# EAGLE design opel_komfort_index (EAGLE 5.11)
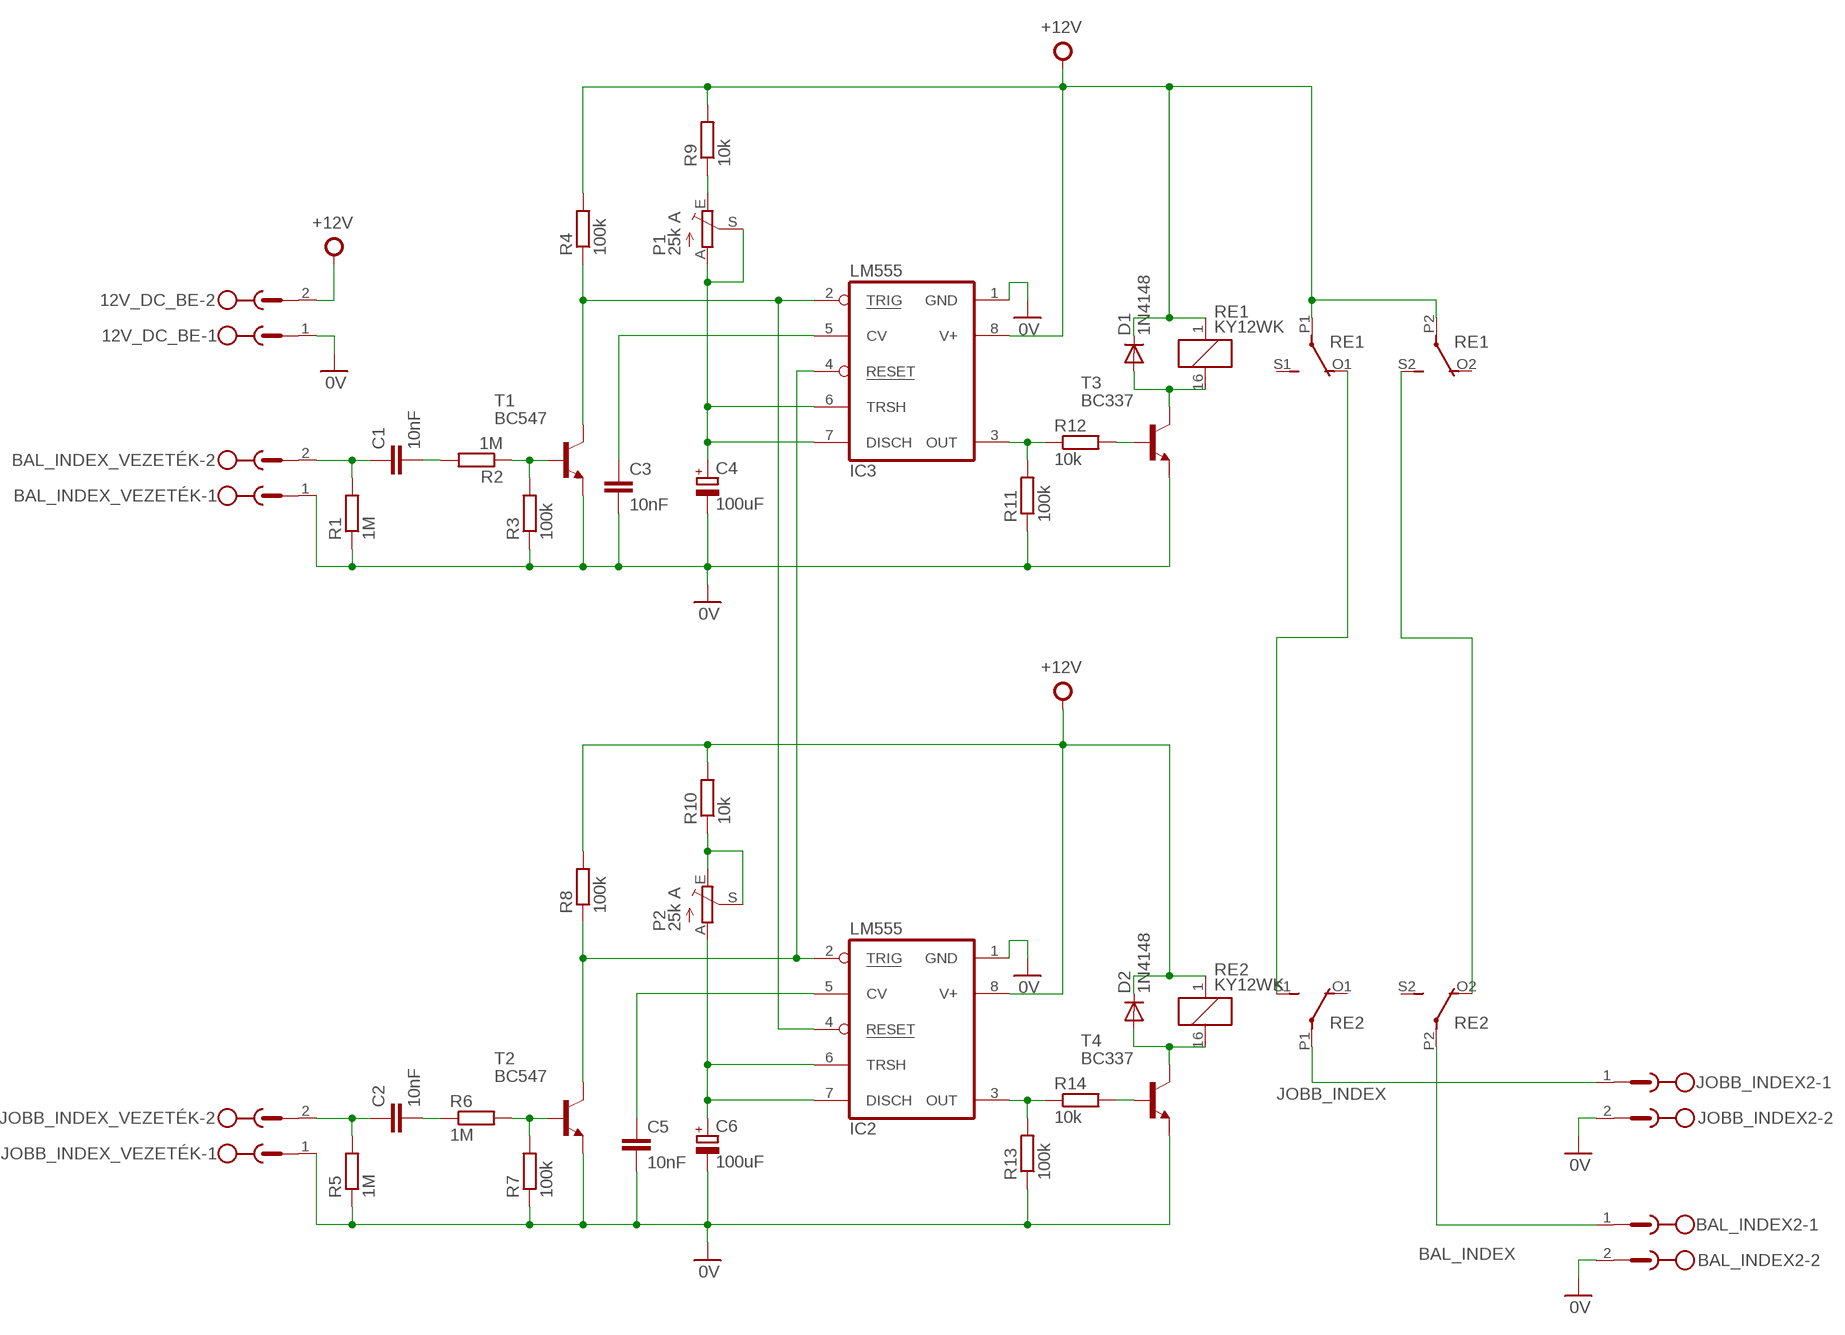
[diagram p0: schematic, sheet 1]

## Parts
12V_DC_BE  MSTBV2  [MSTBV2]
BAL_INDEX2  MSTBV2  [MSTBV2]
BAL_INDEX_VEZETÉK  MSTBV2  [MSTBV2]
C1  10nF  C-EU025-024X044  [C025-024X044]
C2  10nF  C-EU025-024X044  [C025-024X044]
C3  10nF  C-EU025-024X044  [C025-024X044]
C4  100uF  CPOL-EUE2,5-6E  [E2,5-6E]
C5  10nF  C-EU025-024X044  [C025-024X044]
C6  100uF  CPOL-EUE2,5-6E  [E2,5-6E]
D1  1N4148  [DO35-10]
D2  1N4148  [DO35-10]
IC2  LM555  ICM7555  [DIL08]
IC3  LM555  ICM7555  [DIL08]
JOBB_INDEX2  MSTBV2  [MSTBV2]
JOBB_INDEX_VEZETÉK  MSTBV2  [MSTBV2]
P1  25k A  TRIM_EU-CA6H  [CA6H]
P2  25k A  TRIM_EU-CA6H  [CA6H]
R1  1M  R-EU_0204/5  [0204/5]
R2  1M  R-EU_0204/5  [0204/5]
R3  100k  R-EU_0204/5  [0204/5]
R4  100k  R-EU_0204/5  [0204/5]
R5  1M  R-EU_0204/5  [0204/5]
R6  1M  R-EU_0204/5  [0204/5]
R7  100k  R-EU_0204/5  [0204/5]
R8  100k  R-EU_0204/5  [0204/5]
R9  10k  R-EU_0204/5  [0204/5]
R10  10k  R-EU_0204/5  [0204/5]
R11  100k  R-EU_0204/5  [0204/5]
R12  10k  R-EU_0204/5  [0204/5]
R13  100k  R-EU_0204/5  [0204/5]
R14  10k  R-EU_0204/5  [0204/5]
RE1  KY12WK  351  [351]
RE2  KY12WK  351  [351]
T1  BC547  [TO92]
T2  BC547  [TO92]
T3  BC337  [TO92]
T4  BC337  [TO92]

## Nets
0V: 12V_DC_BE.1 BAL_INDEX2.2 BAL_INDEX_VEZETÉK.1 C3.2 C4.- C5.2 C6.- IC2.1(GND) IC3.1(GND) JOBB_INDEX2.2 JOBB_INDEX_VEZETÉK.1 R1.1 R3.1 R5.1 R7.1 R11.1 R13.1 T1.1(E) T2.1(E) T3.1(E) T4.1(E)
+12V: 12V_DC_BE.2 D1.C D2.C IC2.8(V+) IC3.8(V+) R4.2 R8.2 R9.2 R10.2 RE1.1 RE1.P1(2:P) RE1.P2(3:P) RE2.1
BAL_INDEX: BAL_INDEX2.1 RE2.P2(3:P)
JOBB_INDEX: JOBB_INDEX2.1 RE2.P1(2:P)
N$1: BAL_INDEX_VEZETÉK.2 C1.1 R1.2
N$2: C1.2 R2.2
N$3: R2.1 R3.2 T1.2(B)
N$4: IC2.2(TRIG) IC3.4(RESET) R8.1 T2.3(C)
N$5: RE1.O1(2:O) RE2.S1(2:S)
N$6: P1.E R9.1
N$7: IC3.3(OUT) R11.2 R12.1
N$8: R12.2 T3.2(B)
N$9: C3.1 IC3.5(CV)
N$10: C4.+ IC3.6(TRSH) IC3.7(DISCH) P1.A P1.S
N$11: C2.1 JOBB_INDEX_VEZETÉK.2 R5.2
N$12: C2.2 R6.1
N$13: D1.A RE1.16 T3.3(C)
N$14: R6.2 R7.2 T2.2(B)
N$15: IC2.4(RESET) IC3.2(TRIG) R4.1 T1.3(C)
N$16: P2.E P2.S R10.1
N$17: RE1.S2(3:S) RE2.O2(3:O)
N$18: C5.1 IC2.5(CV)
N$24: IC2.3(OUT) R13.2 R14.1
N$27: C6.+ IC2.6(TRSH) IC2.7(DISCH) P2.A
N$28: D2.A RE2.16 T4.3(C)
N$30: R14.2 T4.2(B)
Unconnected: RE1.O2(3:O) RE1.S1(2:S) RE2.O1(2:O) RE2.S2(3:S)

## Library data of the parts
12V_DC_BE BAL_INDEX2 BAL_INDEX_VEZETÉK JOBB_INDEX2 JOBB_INDEX_VEZETÉK = con-phoenix-500:MSTBV2: PHOENIX; OC_FARNELL: unknown; OC_NEWARK: unknown
C1-C3 C5 = Kameleon_2013:C-EU: CAPACITOR, European symbol
C4 C6 = Kameleon_2013:CPOL-EU: POLARIZED CAPACITOR, European symbol
D1 D2 = diode-1:1N4148: DIODE
IC2 IC3 = maxim:ICM7555: TIMER; MF: MAXIM; MPN: ICM7555IPA+; OC_FARNELL: 9663762; OC_NEWARK: 68K4387
P1 P2 = pot:TRIM_EU-: POTENTIOMETER
R1-R14 = Kameleon_2013:R-EU_: RESISTOR, European symbol
RE1 RE2 = relay:351: RELAY 2 x switch, Omron; OC_FARNELL: unknown; OC_NEWARK: unknown
T1 T2 = transistor:BC547: NPN TRANSISTOR
T3 T4 = transistor:BC337: NPN TRANSISTOR

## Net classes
0 default: width 0.635 mm

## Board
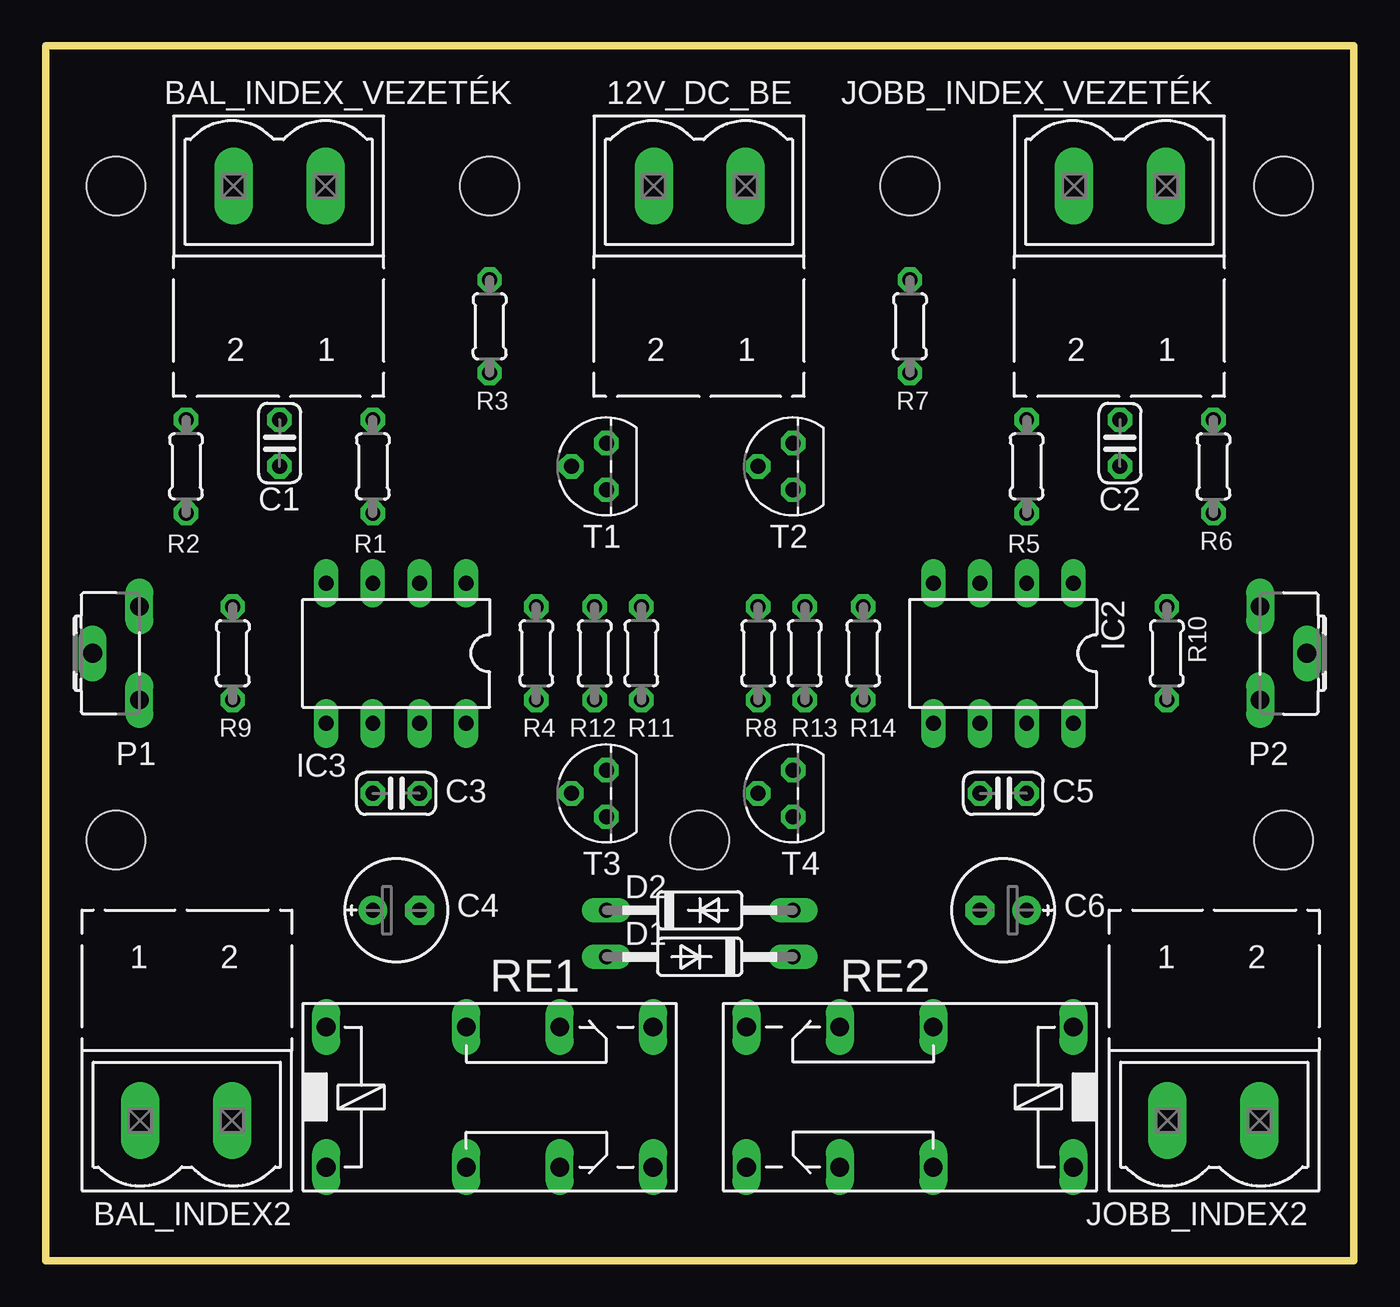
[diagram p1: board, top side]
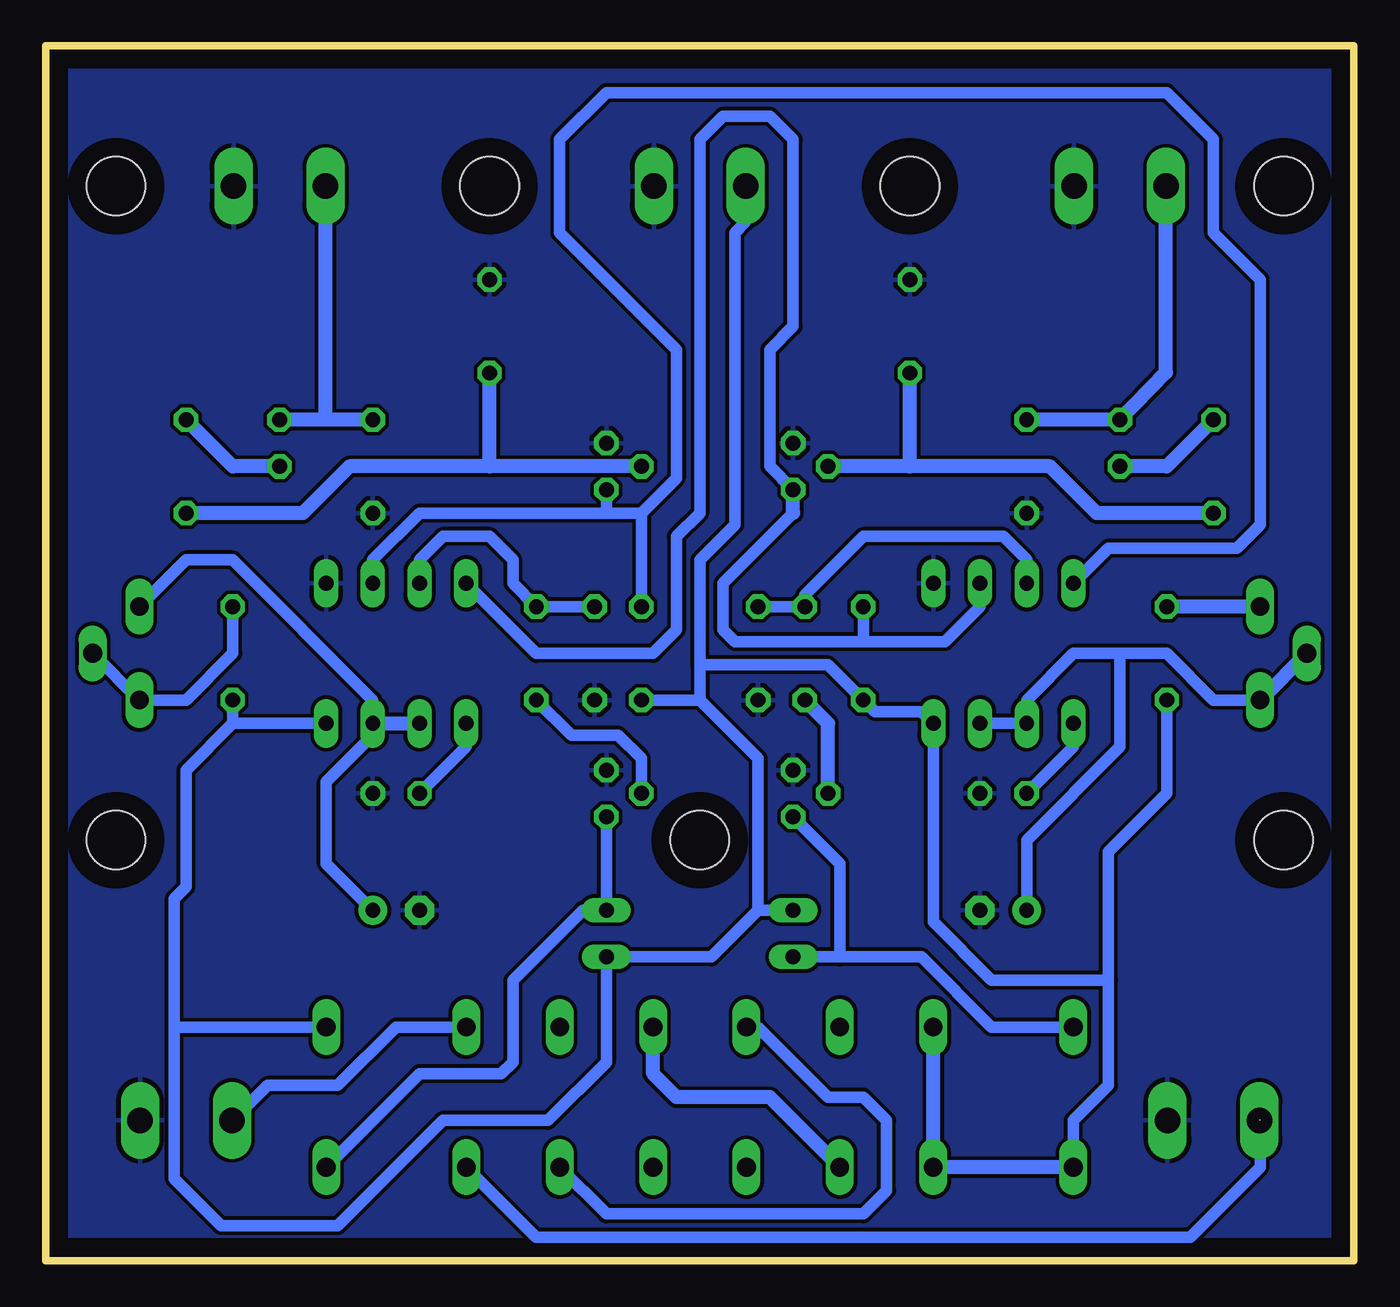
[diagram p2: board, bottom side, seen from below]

Size 71.12 x 66.04 mm. Coordinates in mm from the lower left corner, seen from the top.
Outline: 0,0 71.12,0 71.12,66.04 0,66.04 0,0
Copper layers (1*16): Top 0.035mm / dielectric 1.5mm / Bottom 0.035mm
Design rules "default": minimum track width 10mil, minimum drill 24mil, track to track 8mil, track to pad 8mil, pad to pad 8mil, via to via 8mil, smd to smd 8mil, copper to edge 40mil, drill to drill 8mil, minimum pad ring 10mil, minimum via ring 8mil, stop-mask expansion 4mil, vias tented up to drill 0mil, thermal gap 10mil
Holes 3.2 mm at 3.81,58.42 67.31,58.42 3.81,22.86 67.31,22.86 24.13,58.42 46.99,58.42 35.56,22.86

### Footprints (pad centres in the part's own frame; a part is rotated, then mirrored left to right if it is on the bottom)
MSTBV2 = drill 1.397 long: 1 -2.5,0; 2 2.5,0
C025-024X044 = drill 0.813 octagon: 1 -1.27,0; 2 1.27,0
E2,5-6E = drill 0.813 pad 1.575 round: + -1.27,0 | drill 0.813 pad 1.575 octagon: - 1.27,0
DO35-10 = drill 0.813 long: A 5.08,0; C -5.08,0
DIL08 = drill 0.813 long: 1 -3.81,-3.81; 2 -1.27,-3.81; 3 1.27,-3.81; 4 3.81,-3.81; 5 3.81,3.81; 6 1.27,3.81; 7 -1.27,3.81; 8 -3.81,3.81
CA6H = drill 1.016 long: A -2.54,0; E 2.54,0; S 0,2.54
0204/5 = drill 0.813 octagon: 1 -2.54,0; 2 2.54,0
351 = drill 1.016 long: 1 -3.81,-3.81; 16 -3.81,3.81; O1 8.89,-3.81; O2 8.89,3.81; P1 3.81,-3.81; P2 3.81,3.81; S1 13.97,-3.81; S2 13.97,3.81
TO92 = drill 0.813 octagon: 1 1.27,0; 2 0,1.905; 3 -1.27,0

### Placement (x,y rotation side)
12V_DC_BE  35.56,58.42 180 top
BAL_INDEX2  7.62,7.62 0 top
BAL_INDEX_VEZETÉK  12.7,58.42 180 top
C1  12.7,44.45 270 top
C2  58.42,44.45 270 top
C3  19.05,25.4 0 top
C4  19.05,19.05 0 top
C5  52.07,25.4 0 top
C6  52.07,19.05 180 top
D1  35.56,16.51 180 top
D2  35.56,19.05 0 top
IC2  52.07,33.02 180 top
IC3  19.05,33.02 180 top
JOBB_INDEX2  63.5,7.62 0 top
JOBB_INDEX_VEZETÉK  58.42,58.42 180 top
P1  5.08,33.02 90 top
P2  66.04,33.02 270 top
R1  17.78,43.18 90 top
R2  7.62,43.18 90 top
R3  24.13,50.8 270 top
R4  26.67,33.02 270 top
R5  53.34,43.18 90 top
R6  63.5,43.18 270 top
R7  46.99,50.8 270 top
R8  38.73,33.02 270 top
R9  10.16,33.02 270 top
R10  60.96,33.02 270 top
R11  32.38,33.02 90 top
R12  29.84,33.02 270 top
R13  41.27,33.02 90 top
R14  44.45,33.02 270 top
RE1  19.05,8.89 0 top
RE2  52.07,8.89 180 top
T1  30.48,43.18 90 top
T2  40.64,43.18 90 top
T3  30.48,25.4 90 top
T4  40.64,25.4 90 top

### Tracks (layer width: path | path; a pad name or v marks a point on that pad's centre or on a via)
0V
  pour Bottom (isolate 0.2): -2.54,-2.54 73.66,-2.54 73.66,68.58 -2.54,68.58
+12V
  Bottom 0.635: 64.14,12.7 64.14,4.45 61.59,1.91 55.24,1.91 49.53,7.62 43.81,7.62 40.64,10.79 D1.C 34.92,16.51 32.38,19.05 | 64.14,12.7 64.14,19.68 63.5,20.32 63.5,26.67 60.96,29.21 | 64.14,12.7 RE2.1 | 35.56,30.48 R8.2 | 35.56,32.38 35.56,30.48 | 35.56,32.38 28.57,32.38 R4.2 26.04,29.84 23.5,29.84 IC3.8 22.86,18.41 19.68,15.24 13.34,15.24 | 33.02,58.38 12V_DC_BE.2 33.06,56.48 33.66,55.88 33.66,40.01 35.56,38.1 35.56,32.38 | 13.34,15.24 13.34,9.53 15.24,7.62 RE1.1 | 13.34,15.24 13.34,22.23 10.16,25.4 R9.2 | 32.38,19.05 D2.C | 60.96,29.21 IC2.8 | 60.96,29.21 R10.2 | 35.56,30.48 32.38,27.3 32.38,19.05
  Bottom 0.762: RE1.1 RE1.P1 RE1.P2
BAL_INDEX  (1 unrouted)
  Bottom 0.635: 5.08,7.62 5.08,5.08 8.89,1.27 44.45,1.27 RE2.P2
JOBB_INDEX
  Bottom 0.635: RE2.P1 52.07,12.7 55.24,9.53 59.05,9.53 60.96,7.62 JOBB_INDEX2.1
N$1
  Bottom 0.762: BAL_INDEX_VEZETÉK.2 10.2,48.3 C1.1 R1.2
N$2
  Bottom 0.762: C1.2 10.16,43.18 R2.2
N$3
  Bottom 0.762: 24.13,43.18 T1.2 | R2.1 13.97,40.64 16.51,43.18 24.13,43.18 | 24.13,43.18 R3.2
N$4
  Bottom 0.635: IC2.2 53.34,38.1 50.8,40.64 40.64,40.64 | 38.73,40.64 36.83,42.55 36.83,49.53 43.18,55.88 43.18,60.96 40.64,63.5 10.16,63.5 7.62,60.96 7.62,55.88 5.08,53.34 5.08,40.01 6.35,38.73 13.34,38.73 IC3.4 | 38.73,40.64 40.64,40.64 | 38.73,40.64 R8.1 | 40.64,40.64 T2.3
N$5
  Bottom 0.762: RE1.O1 31.75,8.89 36.83,8.89 38.1,10.16 RE2.S1
N$6
  Bottom 0.762: P1.E R9.1
N$7
  Bottom 0.635: R11.2 R12.1 29.84,36.2 26.67,39.37 19.05,39.37 17.78,38.1 IC3.3
N$8
  Bottom 0.762: T3.2 28.57,29.21 R12.2
N$9
  Bottom 0.635: IC3.5 15.24,27.94 C3.1
N$10
  Bottom 0.635: P1.A 7.62,30.48 10.16,33.02 12.7,33.02 | C4.+ 17.78,22.86 12.7,27.94 12.7,33.02 | 12.7,33.02 15.24,33.02 17.78,30.48 IC3.6 IC3.7
  Bottom 0.762: P1.S P1.A
N$11
  Bottom 0.762: R5.2 55.88,45.72 | 55.88,45.72 C2.1 | JOBB_INDEX_VEZETÉK.2 55.92,45.76 55.88,45.72
N$12
  Bottom 0.762: C2.2 60.96,43.18 R6.1
N$13
  Bottom 0.635: RE1.16 19.68,12.7 23.5,16.51 27.94,16.51 | 27.94,16.51 D1.A | T3.3 27.94,21.59 27.94,16.51
N$14
  Bottom 0.762: R6.2 57.15,40.64 54.61,43.18 46.99,43.18 | T2.2 46.99,43.18 | 46.99,43.18 R7.2
N$15
  Bottom 0.635: 26.67,33.66 33.66,33.66 34.29,34.29 34.29,36.83 30.48,40.64 | 26.67,33.66 R4.1 | IC2.4 44.45,33.02 38.1,33.02 36.83,34.29 36.83,39.37 35.56,40.64 35.56,60.96 34.29,62.23 31.75,62.23 30.48,60.96 30.48,50.8 31.75,49.53 31.75,43.18 T1.3 | 26.67,33.66 22.23,33.66 20.32,35.56 IC3.2
  Bottom 0.762: 30.48,40.64 T1.3
N$16
  Bottom 0.635: R10.1 60.96,33.02 63.5,30.48 P2.E P2.S
N$17
  Bottom 0.635: RE1.S2 32.38,12.7 28.57,8.89 26.67,8.89 25.4,7.62 25.4,3.81 26.67,2.54 40.64,2.54 RE2.O2
N$18
  Bottom 0.635: IC2.5 48.26,27.94 C5.1
N$24
  Bottom 0.635: IC2.3 50.8,38.1 49.53,39.37 46.99,39.37 45.72,38.1 45.72,36.83 R14.1 R13.2
N$27
  Bottom 0.635: C6.+ 55.88,21.59 55.88,26.04 53.34,28.57 IC2.7 53.34,30.48 60.96,38.1 63.5,38.1 P2.A
  Bottom 0.762: IC2.7 IC2.6
N$28
  Bottom 0.635: RE2.16 50.8,10.16 46.35,10.16 45.72,10.79 45.72,15.24 43.18,17.78 41.91,19.05 D2.A T4.3
N$30
  Bottom 0.635: T4.2 38.73,27.3 40.01,28.57 42.55,28.57 R14.2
